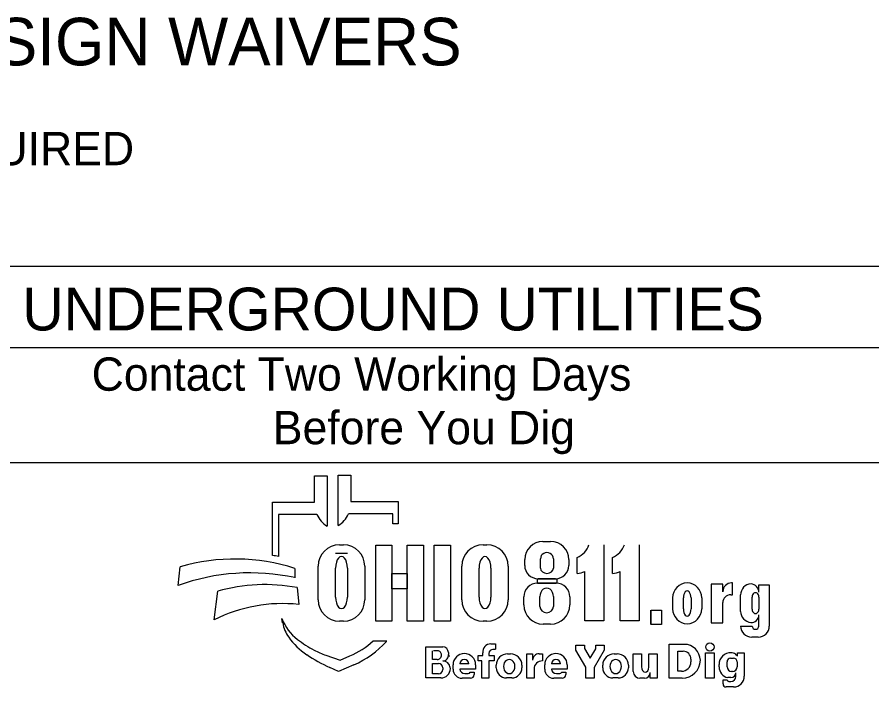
# Model space of a CAD drawing. Extents: x -5.6 to 34, y 0 to 22.
# Drawn here: x 3.084 to 6.676, y 2.711 to 5.529 of the extents above; entities that cross this region are included whole.
import ezdxf

# ---------------------------------------------------------------- set-up
doc = ezdxf.new("R2010")
doc.units = 0
doc.layers.add('SH_Data', color=7, linetype='Continuous')
doc.layers.add('SH_Text', color=7, linetype='Continuous')

msp = doc.modelspace()

# ---------------------------------------------------------------- linework, layer by layer
at = {"layer": 'SH_Data'}
for p, q in [((7.2275, 4.4803), (2.9775, 4.4803)), ((2.9775, 4.1387), (7.2275, 4.1387)), ((2.9775, 3.6553), (7.2275, 3.6553))]:
    msp.add_line(p, q, dxfattribs=at)
at = {"layer": 'SH_Text'}
for p, q in [((4.3335, 3.4883), (4.3335, 3.5998)), ((4.3335, 3.5998), (4.3872, 3.5998)), ((4.3872, 3.5998), (4.3872, 3.3877)), ((4.4329, 3.39), (4.4329, 3.6021)), ((4.4329, 3.6021), (4.4865, 3.6021)), ((4.4865, 3.6021), (4.4865, 3.4906)), ((4.1576, 3.2644), (4.1576, 3.4883)), ((4.1576, 3.4883), (4.3335, 3.4883)), ((4.4865, 3.4906), (4.6857, 3.4906)), ((4.6857, 3.4906), (4.6857, 3.3968)), ((4.1828, 3.4369), (4.1828, 3.26)), ((4.3439, 3.4369), (4.1828, 3.4369)), ((4.6625, 3.4392), (4.4761, 3.4392)), ((4.6625, 3.3968), (4.6625, 3.4392)), ((4.6857, 3.3968), (4.6625, 3.3968)), ((4.4385, 3.3091), (4.4551, 3.3091)), ((5.0416, 3.3091), (5.0581, 3.3091)), ((5.2931, 3.3231), (5.3258, 3.3231)), ((5.5487, 3.3087), (5.5487, 2.9887)), ((5.6975, 3.3087), (5.6975, 2.9887)), ((4.4718, 3.2721), (4.422, 3.2721)), ((5.2168, 3.2225), (5.2168, 3.2468)), ((5.283, 3.2111), (5.283, 3.2504)), ((5.3371, 3.2504), (5.3371, 3.2111)), ((5.4022, 3.2468), (5.4022, 3.2225)), ((5.4371, 3.188), (5.4371, 3.2562)), ((5.5859, 3.188), (5.5859, 3.2562)), ((3.7602, 3.1381), (3.7696, 3.2162)), ((4.2509, 3.2097), (4.2509, 3.1709)), ((4.3491, 3.0776), (4.3491, 3.2196)), ((4.422, 3.089), (4.422, 3.2114)), ((4.4718, 3.2114), (4.4718, 3.089)), ((4.5445, 3.2196), (4.5445, 3.0776)), ((4.9521, 3.0776), (4.9521, 3.2196)), ((5.025, 3.089), (5.025, 3.2114)), ((5.0748, 3.2114), (5.0748, 3.089)), ((5.1476, 3.2196), (5.1476, 3.0776)), ((5.4694, 2.9887), (5.4694, 3.1973)), ((5.6182, 2.9887), (5.6182, 3.1973)), ((5.3462, 3.1665), (5.2728, 3.1665)), ((4.2608, 3.1291), (4.2671, 3.0582)), ((5.271, 3.1482), (5.3483, 3.1482)), ((6.0493, 3.1436), (6.0005, 3.1436)), ((6.0005, 3.1436), (6.0005, 2.9806)), ((6.0493, 3.112), (6.0493, 3.1436)), ((6.09, 3.1487), (6.086, 3.1487)), ((6.09, 3.0989), (6.09, 3.1487)), ((6.2009, 3.1094), (6.2009, 3.1404)), ((6.2009, 3.1404), (6.2444, 3.1404)), ((6.2444, 3.1404), (6.2444, 2.9675)), ((3.912, 2.9936), (3.9267, 3.1137)), ((5.2131, 3.0563), (5.2131, 3.0903)), ((5.2806, 3.0503), (5.2806, 3.0912)), ((5.3374, 3.0912), (5.3374, 3.0503)), ((5.4062, 3.0903), (5.4062, 3.0563)), ((6.0823, 3.0989), (6.09, 3.0989)), ((6.1239, 3.029), (6.1239, 3.0986)), ((6.1723, 3.0383), (6.1723, 3.0893)), ((6.2009, 3.0893), (6.2009, 3.0383)), ((5.8385, 3.0404), (5.8385, 3.0858)), ((5.8835, 3.0396), (5.8835, 3.0858)), ((5.9157, 3.0858), (5.9157, 3.0396)), ((5.9606, 3.0858), (5.9606, 3.0404)), ((6.0493, 2.9806), (6.0493, 3.0659)), ((5.7456, 3.0337), (5.7456, 2.9737)), ((4.1997, 2.9807), (4.1967, 2.9986)), ((4.4551, 2.9882), (4.4385, 2.9882)), ((5.0581, 2.9882), (5.0416, 2.9882)), ((5.5487, 2.9887), (5.4694, 2.9887)), ((5.6975, 2.9887), (5.6182, 2.9887)), ((6.2009, 2.9675), (6.2009, 3.0139)), ((5.3252, 2.9753), (5.2941, 2.9753)), ((6.0005, 2.9806), (6.0493, 2.9806)), ((6.1239, 2.9675), (6.1723, 2.9675)), ((6.1977, 2.9208), (6.1707, 2.9208)), ((4.58, 2.9048), (4.6375, 2.9048)), ((4.8013, 2.749), (4.8013, 2.8798)), ((4.8013, 2.8798), (4.8725, 2.8798)), ((5.0739, 2.8926), (5.0934, 2.8926)), ((5.0934, 2.8926), (5.0934, 2.8696)), ((5.4319, 2.887), (5.4677, 2.887)), ((5.4319, 2.8655), (5.4319, 2.887)), ((5.4677, 2.887), (5.4677, 2.8734)), ((5.5151, 2.8719), (5.5151, 2.887)), ((5.5151, 2.887), (5.5509, 2.887)), ((5.5509, 2.887), (5.5509, 2.8655)), ((5.8243, 2.8906), (5.8866, 2.8906)), ((5.8243, 2.7478), (5.8243, 2.8906)), ((4.3816, 2.8444), (4.441, 2.8239)), ((4.441, 2.8239), (4.4821, 2.8417)), ((4.8293, 2.8263), (4.8293, 2.8632)), ((4.8545, 2.8632), (4.8332, 2.8632)), ((4.8963, 2.856), (4.8963, 2.8481)), ((5.0213, 2.8212), (5.0213, 2.8442)), ((5.0213, 2.8442), (5.0406, 2.8442)), ((5.0406, 2.8442), (5.0406, 2.8546)), ((5.0667, 2.8526), (5.0667, 2.8442)), ((5.0667, 2.8442), (5.0883, 2.8442)), ((5.0934, 2.8691), (5.0832, 2.8691)), ((5.0883, 2.8442), (5.0883, 2.8212)), ((5.1451, 2.8508), (5.1573, 2.8508)), ((5.2254, 2.7478), (5.2254, 2.8505)), ((5.2254, 2.8505), (5.2499, 2.8505)), ((5.2499, 2.8505), (5.2499, 2.8237)), ((5.2772, 2.8505), (5.291, 2.8505)), ((5.291, 2.8505), (5.291, 2.8209)), ((5.4732, 2.7946), (5.4319, 2.8655)), ((5.4677, 2.8734), (5.4918, 2.832)), ((5.4918, 2.832), (5.5151, 2.8719)), ((5.5509, 2.8655), (5.5088, 2.7932)), ((5.5925, 2.8508), (5.6047, 2.8508)), ((5.6727, 2.8508), (5.7075, 2.8508)), ((5.6727, 2.7762), (5.6727, 2.8508)), ((5.7075, 2.8508), (5.7075, 2.7954)), ((5.7388, 2.7938), (5.7388, 2.8508)), ((5.7388, 2.8508), (5.7736, 2.8508)), ((5.7736, 2.8508), (5.7736, 2.7478)), ((5.8603, 2.7773), (5.8603, 2.8613)), ((5.8603, 2.8613), (5.8828, 2.8613)), ((5.977, 2.8549), (6.0126, 2.8549)), ((5.977, 2.7478), (5.977, 2.8549)), ((6.0126, 2.8549), (6.0126, 2.7478)), ((6.1021, 2.8493), (6.1107, 2.8427)), ((6.1107, 2.8553), (6.1395, 2.8553)), ((6.1107, 2.8427), (6.1107, 2.8553)), ((6.1107, 2.8553), (6.1395, 2.8553)), ((6.1395, 2.8553), (6.1395, 2.7567)), ((4.4983, 2.8044), (4.435, 2.7769)), ((4.8487, 2.8263), (4.8293, 2.8263)), ((4.8293, 2.7669), (4.8293, 2.8097)), ((4.8293, 2.8097), (4.8548, 2.8097)), ((4.9159, 2.7858), (4.9159, 2.8042)), ((4.9824, 2.8082), (4.9439, 2.8082)), ((5.0104, 2.8042), (5.0104, 2.7866)), ((5.0362, 2.8212), (5.0213, 2.8212)), ((5.0362, 2.7478), (5.0362, 2.8212)), ((5.0883, 2.8212), (5.0667, 2.8212)), ((5.0667, 2.8212), (5.0667, 2.7478)), ((5.0973, 2.7922), (5.0973, 2.8029)), ((5.2051, 2.8029), (5.2051, 2.7922)), ((5.3008, 2.7858), (5.3008, 2.8042)), ((5.3674, 2.8082), (5.3288, 2.8082)), ((5.3953, 2.8042), (5.3953, 2.7866)), ((5.5447, 2.7922), (5.5447, 2.8029)), ((5.6525, 2.8029), (5.6525, 2.7922)), ((5.9154, 2.8286), (5.9154, 2.8168)), ((6.0335, 2.7953), (6.0335, 2.8054)), ((6.067, 2.7961), (6.067, 2.8173)), ((6.0816, 2.8319), (6.0944, 2.8319)), ((6.109, 2.8173), (6.109, 2.7961)), ((4.435, 2.7769), (4.3976, 2.7934)), ((4.8546, 2.7669), (4.8293, 2.7669)), ((4.8729, 2.7916), (4.8729, 2.7853)), ((4.9043, 2.7887), (4.9043, 2.7884)), ((5.0104, 2.7866), (4.944, 2.7866)), ((4.9649, 2.7673), (4.979, 2.7673)), ((4.9876, 2.7729), (5.0045, 2.7729)), ((5.0045, 2.7729), (5.0045, 2.7631)), ((5.2559, 2.786), (5.2559, 2.7478)), ((5.3953, 2.7866), (5.3289, 2.7866)), ((5.3498, 2.7673), (5.3639, 2.7673)), ((5.3725, 2.7729), (5.3894, 2.7729)), ((5.3894, 2.7729), (5.3894, 2.7631)), ((5.4732, 2.7478), (5.4732, 2.7946)), ((5.5088, 2.7932), (5.5088, 2.7478)), ((5.7439, 2.7478), (5.7439, 2.7719)), ((5.8759, 2.7773), (5.8603, 2.7773)), ((6.0897, 2.7768), (6.0863, 2.7768)), ((6.1039, 2.7557), (6.1039, 2.7711)), ((4.865, 2.749), (4.8013, 2.749)), ((4.9892, 2.7478), (4.9538, 2.7478)), ((5.0667, 2.7478), (5.0362, 2.7478)), ((5.1623, 2.7494), (5.1401, 2.7494)), ((5.2559, 2.7478), (5.2254, 2.7478)), ((5.3742, 2.7478), (5.3388, 2.7478)), ((5.5088, 2.7478), (5.4732, 2.7478)), ((5.6097, 2.7494), (5.5875, 2.7494)), ((5.7199, 2.7478), (5.7011, 2.7478)), ((5.7736, 2.7478), (5.7439, 2.7478)), ((5.8779, 2.7478), (5.8243, 2.7478)), ((6.0126, 2.7478), (5.977, 2.7478)), ((6.05, 2.7245), (6.05, 2.7415)), ((6.05, 2.7415), (6.067, 2.7415)), ((6.0835, 2.7506), (6.0698, 2.7506)), ((6.0738, 2.7345), (6.0827, 2.7345)), ((6.0942, 2.7114), (6.0631, 2.7114))]:
    msp.add_line(p, q, dxfattribs=at)
for points in [[(4.591, 3.3081), (4.6589, 3.3081), (4.6589, 2.9881), (4.591, 2.9881)], [(4.7231, 3.3081), (4.7911, 3.3081), (4.7911, 2.9881), (4.7231, 2.9881)], [(4.8364, 3.3081), (4.9052, 3.3081), (4.9052, 2.9881), (4.8364, 2.9881)], [(4.6589, 3.1882), (4.7231, 3.1882), (4.7231, 3.1242), (4.6589, 3.1242)], [(5.2706, 3.1665), (5.3523, 3.1665), (5.3523, 3.1481), (5.2706, 3.1481)], [(5.748, 3.0337), (5.7921, 3.0337), (5.7921, 2.9737), (5.748, 2.9737)]]:
    msp.add_lwpolyline(points, close=True, dxfattribs=at)
msp.add_circle((5.9952, 2.8793), 0.0177, dxfattribs=at)
for centre, radius, start, end in [((4.4353, 3.4736), 0.0985, 201.9296, 240.7469), ((4.3847, 3.476), 0.0985, 299.2531, 338.0704), ((4.4385, 3.2196), 0.0895, 90, 180), ((4.4551, 3.2196), 0.0895, 0, 90), ((5.0416, 3.2196), 0.0895, 90, 180), ((5.0581, 3.2196), 0.0895, 0, 90), ((5.2931, 3.2468), 0.0763, 90, 180), ((5.3258, 3.2468), 0.0763, 0, 90), ((5.4031, 3.3379), 0.0885, 292.5572, 340.7355), ((5.552, 3.3379), 0.0885, 292.5572, 340.7355), ((3.9997, 2.4302), 0.8191, 72.1402, 106.3144), ((4.0295, 2.4554), 0.8191, 79.2074, 81.0007), ((5.2728, 3.2225), 0.056, 180, 270), ((5.3462, 3.2225), 0.056, 270, 0), ((5.4291, 3.2761), 0.0885, 275.1733, 297.0931), ((5.5779, 3.2761), 0.0885, 275.1733, 297.0931), ((4.0628, 2.2991), 0.8919, 77.8238, 109.8274), ((4.1267, 2.4094), 0.7322, 79.44, 105.8467), ((5.271, 3.0903), 0.0579, 90, 180), ((5.3483, 3.0903), 0.0579, 0, 90), ((5.9024, 3.0858), 0.064, 92.5886, 180), ((5.8967, 3.0858), 0.064, 0, 87.4114), ((6.086, 3.112), 0.0367, 90, 180), ((6.1698, 3.0986), 0.0459, 92.6865, 180), ((6.1658, 3.1094), 0.0351, 0, 86.9262), ((6.0823, 3.0659), 0.033, 90, 180), ((4.1987, 2.4262), 0.6357, 83.8248, 116.8021), ((4.4385, 3.0776), 0.0895, 180, 270), ((4.4551, 3.0776), 0.0895, 270, 0), ((5.0416, 3.0776), 0.0895, 180, 270), ((5.0581, 3.0776), 0.0895, 270, 0), ((5.2941, 3.0563), 0.081, 180, 270), ((5.3252, 3.0563), 0.081, 270, 0), ((5.9024, 3.0404), 0.064, 180, 267.4114), ((5.8967, 3.0404), 0.064, 272.5886, 0), ((6.1702, 3.029), 0.0463, 180, 265.7132), ((4.3841, 3.0707), 0.2008, 201.0457, 232.5314), ((6.1696, 3.0139), 0.0313, 264.7825, 0), ((4.341, 3.0048), 0.1433, 189.6817, 216.0884), ((6.1707, 2.9675), 0.0468, 180, 270), ((6.1977, 2.9675), 0.0468, 270, 0), ((4.4747, 3.1022), 0.3088, 216.0884, 235.7167), ((4.5766, 3.3219), 0.5173, 232.5314, 241.794), ((4.3387, 3.1722), 0.3602, 293.4582, 312.0712), ((4.3387, 3.1722), 0.401, 293.4582, 317.8286), ((4.8725, 2.856), 0.0238, 0, 90), ((5.0739, 2.859), 0.0335, 90, 187.5187), ((5.8866, 2.8223), 0.0682, 0.9944, 90), ((4.6412, 3.3465), 0.6044, 235.7167, 246.2325), ((4.4914, 3.1631), 0.3371, 241.794, 250.9821), ((4.8487, 2.845), 0.0187, 270, 2.0582), ((4.8505, 2.8463), 0.0169, 357.8325, 90), ((4.8721, 2.8453), 0.0243, 270, 6.6529), ((4.8827, 2.8438), 0.0175, 347.4023, 0), ((4.9631, 2.8042), 0.0473, 0, 180), ((5.0832, 2.8526), 0.0165, 90, 180), ((5.1451, 2.8029), 0.0478, 90, 180), ((5.1573, 2.8029), 0.0478, 0, 90), ((5.2768, 2.8237), 0.0269, 89.2449, 180), ((5.3481, 2.8042), 0.0473, 0, 180), ((5.5925, 2.8029), 0.0478, 90, 180), ((5.6047, 2.8029), 0.0478, 0, 90), ((5.8828, 2.8286), 0.0327, 0, 90), ((6.0834, 2.8054), 0.0499, 89.0934, 180), ((6.0848, 2.827), 0.0283, 52.1415, 91.2046), ((4.8548, 2.7916), 0.0181, 0, 90), ((4.8722, 2.7889), 0.0321, 4.0748, 90), ((4.9632, 2.8072), 0.0193, 2.9632, 177.0368), ((5.2908, 2.786), 0.0349, 89.6033, 180), ((5.3481, 2.8072), 0.0193, 2.9632, 177.0368), ((5.8759, 2.8168), 0.0395, 270, 0), ((5.8779, 2.8248), 0.0769, 270, 359.0635), ((6.0816, 2.8173), 0.0146, 90, 180), ((6.0944, 2.8173), 0.0146, 0, 90), ((4.8546, 2.7853), 0.0184, 270, 0), ((4.865, 2.7884), 0.0393, 270, 0), ((4.8714, 2.7887), 0.033, 0, 11.7502), ((4.9538, 2.7858), 0.038, 180, 270), ((4.9649, 2.7883), 0.021, 184.827, 270), ((4.979, 2.7767), 0.00938, 270, 335.9979), ((5.1401, 2.7922), 0.0428, 180, 270), ((5.1623, 2.7922), 0.0428, 270, 0), ((5.3388, 2.7858), 0.038, 180, 270), ((5.3498, 2.7883), 0.021, 184.827, 270), ((5.3639, 2.7767), 0.00938, 270, 335.9979), ((5.5875, 2.7922), 0.0428, 180, 270), ((5.6097, 2.7922), 0.0428, 270, 0), ((5.7011, 2.7762), 0.0284, 180, 270), ((5.7199, 2.7719), 0.024, 270, 0), ((6.0791, 2.7953), 0.0457, 180, 258.2203), ((6.0863, 2.7961), 0.0193, 180, 270), ((6.0835, 2.771), 0.0203, 270, 0), ((6.0897, 2.7961), 0.0193, 270, 0), ((4.9892, 2.7631), 0.0152, 270, 0), ((5.3742, 2.7631), 0.0152, 270, 0), ((6.0738, 2.7413), 0.00682, 180, 270), ((6.0827, 2.7557), 0.0212, 270, 0), ((6.0942, 2.7567), 0.0453, 270, 0), ((6.0631, 2.7245), 0.0131, 180, 270)]:
    msp.add_arc(centre, radius, start, end, dxfattribs=at)
for centre, major_axis, ratio, start_param, end_param in [((5.31, 3.2504), (0.0271, 0), 0.969373, 0, 3.141593), ((4.4469, 3.2114), (0, 0.0484), 0.514403, 4.712389, 7.853982), ((5.0499, 3.2114), (0, 0.0484), 0.514403, 4.712389, 7.853982), ((5.31, 3.2111), (0.0271, 0), 0.818453, 3.141593, 6.283185), ((5.309, 3.0912), (0, 0.0358), 0.794529, 4.712389, 7.853982), ((4.4469, 3.089), (0, 0.0484), 0.514403, 1.570796, 4.712389), ((5.0499, 3.089), (0, 0.0484), 0.514403, 1.570796, 4.712389), ((5.8996, 3.0858), (0, 0.0291), 0.553236, 4.712389, 7.853982), ((6.1866, 3.0893), (0, 0.0184), 0.777179, 4.712389, 7.853982), ((5.309, 3.0503), (0.0284, 0), 0.959837, 3.141593, 6.283185), ((5.8996, 3.0396), (0, 0.0308), 0.522014, 1.570796, 4.712389), ((6.1866, 3.0383), (0, 0.0184), 0.777179, 1.570796, 4.712389), ((6.1866, 2.9675), (0.0143, 0), 0.959012, 3.141593, 6.283185), ((5.1517, 2.7976), (0, 0.029), 0.832186, 4.712389, 7.853982), ((5.5991, 2.7976), (0, 0.029), 0.832186, 4.712389, 7.853982), ((5.1517, 2.7976), (0, 0.0302), 0.797287, 1.570796, 4.712389), ((5.5991, 2.7976), (0, 0.0302), 0.797287, 1.570796, 4.712389), ((5.7231, 2.7962), (-0.0011, 0.0231), 0.679042, 1.570796, 4.575961)]:
    msp.add_ellipse(centre, major_axis=major_axis, ratio=ratio, start_param=start_param, end_param=end_param, dxfattribs=at)

# ---------------------------------------------------------------- texts
for s, height, p in [('ADA DESIGN WAIVERS', 0.2, (1.9944, 5.3256)), ('NONE REQUIRED', 0.14, (1.9944, 4.9056)), ('UNDERGROUND UTILITIES', 0.18, (3.1057, 4.2106)), ('Contact Two Working Days', 0.14, (3.3972, 3.9571)), ('Before You Dig', 0.14, (4.1583, 3.7321))]:
    msp.add_text(s, height=height, dxfattribs=at).set_placement(p)

doc.saveas('drawing.dxf')
